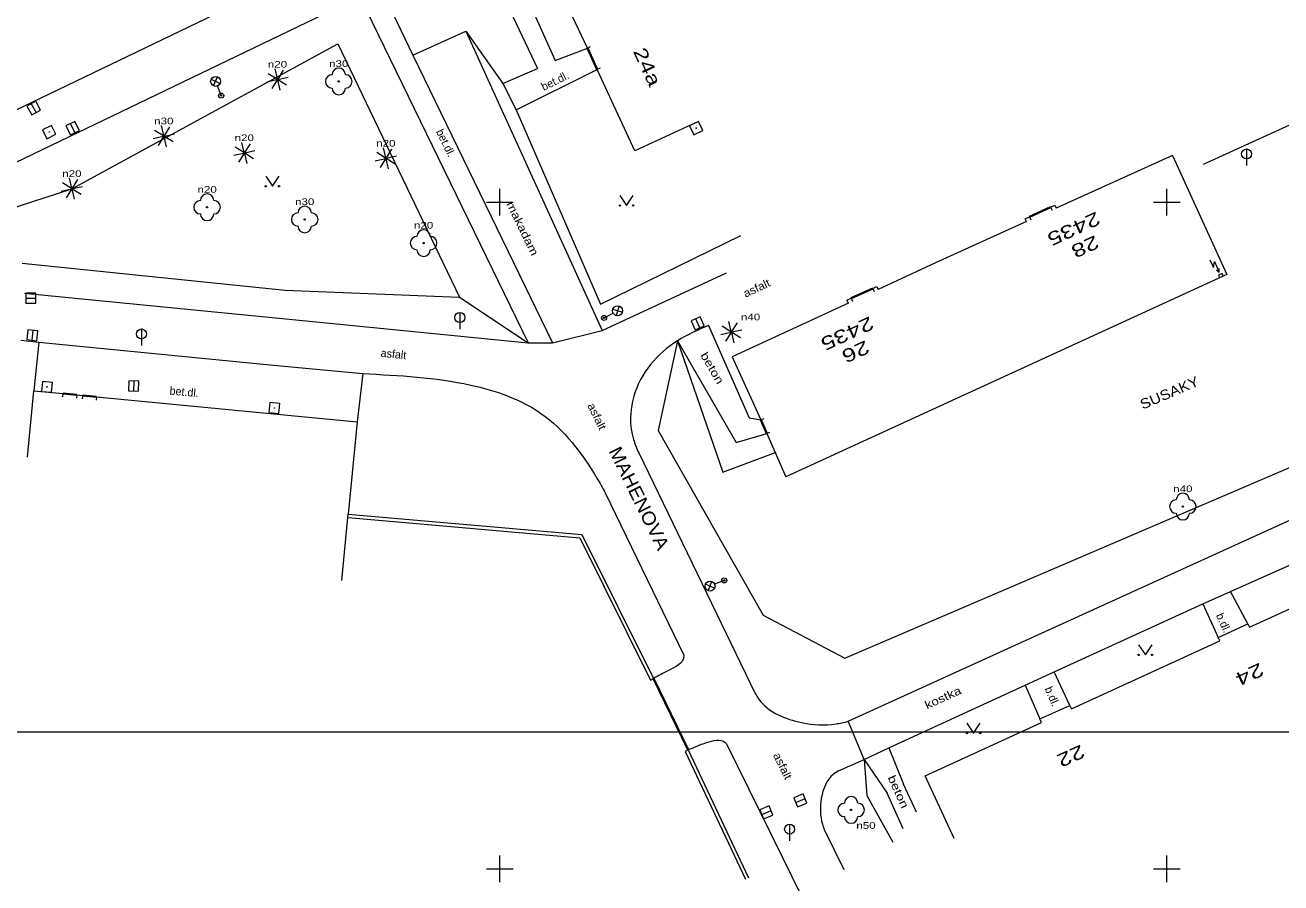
# Model space of a CAD drawing. Extents: x -670514 to -669423, y -1130798 to -1130123.
# Drawn here: x -670285.6 to -670191.5, y -1130401 to -1130336.7 of the extents above; entities that cross this region are included whole.
import ezdxf
from ezdxf.enums import TextEntityAlignment as Align

# ---------------------------------------------------------------- set-up
doc = ezdxf.new("R2010")
doc.units = 0
doc.header["$LTSCALE"] = 0.24
for name, color, linetype, lineweight in [('10', 7, 'Continuous', 13), ('11', 7, 'Continuous', 13), ('14', 7, 'Continuous', 13), ('22', 7, 'Continuous', 13), ('24', 7, 'Continuous', 13), ('26', 7, 'Continuous', 13), ('27', 7, 'Continuous', 13), ('33', 7, 'Continuous', 13), ('36', 7, 'Continuous', 13), ('45', 7, 'Continuous', 13), ('5', 7, 'Continuous', 13), ('6', 7, 'Continuous', 13), ('60', 7, 'Continuous', 13), ('61', 7, 'Continuous', 13), ('7', 7, 'Continuous', 13), ('8', 7, 'Continuous', 13)]:
    doc.layers.add(name, color=color, linetype=linetype, lineweight=lineweight)
for name, color, linetype in [('40', 7, 'Continuous'), ('42', 7, 'Continuous'), ('43', 7, 'Continuous'), ('44', 7, 'Continuous')]:
    doc.layers.add(name, color=color, linetype=linetype)

msp = doc.modelspace()

# ---------------------------------------------------------------- linework, layer by layer
at = {"layer": '10'}
for p, q in [((-670306.368, -1130352.764), (-670262.03, -1130331.413)), ((-670249.16, -1130332.047), (-670245.842, -1130339.387)), ((-670250.594, -1130332.729), (-670247.171, -1130339.983)), ((-670258.985, -1130333.841), (-670256.523, -1130338.99)), ((-670260.5, -1130334.581), (-670247.888, -1130360.543)), ((-670245.842, -1130339.387), (-670243.439, -1130338.448)), ((-670197.261, -1130347.166), (-670179.752, -1130339.172)), ((-670249.779, -1130341.113), (-670247.171, -1130339.983)), ((-670242.338, -1130359.631), (-670233.008, -1130355.298)), ((-670285.636, -1130356.823), (-670266.032, -1130358.753)), ((-670266.032, -1130358.753), (-670247.888, -1130360.543)), ((-670284.549, -1130360.498), (-670284.93, -1130364.149)), ((-670236.685, -1130360.389), (-670232.286, -1130368.017)), ((-670266.966, -1130362.23), (-670260.264, -1130362.861)), ((-670260.264, -1130362.861), (-670260.702, -1130366.465)), ((-670232.286, -1130368.017), (-670229.982, -1130367.337)), ((-670239.589, -1130368.794), (-670230.857, -1130386.843)), ((-670242.093, -1130371.791), (-670236.207, -1130383.981)), ((-670223.892, -1130388.929), (-670187.75, -1130372.448)), ((-670193.933, -1130381.622), (-670195.226, -1130379.206)), ((-670208.448, -1130385.217), (-670197.293, -1130380.124)), ((-670197.293, -1130380.124), (-670196.152, -1130382.65)), ((-670207.274, -1130387.732), (-670208.448, -1130385.217)), ((-670220.831, -1130390.914), (-670210.614, -1130386.221)), ((-670210.614, -1130386.221), (-670209.521, -1130388.748)), ((-670233.018, -1130390.607), (-670228.834, -1130399.092)), ((-670220.831, -1130390.914), (-670219.732, -1130393.646)), ((-670224.601, -1130392.647), (-670222.695, -1130391.791)), ((-670222.695, -1130391.791), (-670220.972, -1130394.327)), ((-670218.77, -1130395.747), (-670219.732, -1130393.646)), ((-670219.754, -1130396.986), (-670220.972, -1130394.327)), ((-670225.672, -1130397.1), (-670224.218, -1130400.048)), ((-670228.834, -1130399.092), (-670227.38, -1130402.04))]:
    msp.add_line(p, q, dxfattribs=at)
for points in [[(-670305.915, -1130356.591), (-670300.884, -1130354.022), (-670260.5, -1130334.581)], [(-670256.523, -1130338.99), (-670252.546, -1130337.184), (-670242.338, -1130359.631)], [(-670249.779, -1130341.113), (-670248.785, -1130343.091), (-670242.698, -1130340.067)], [(-670234.362, -1130359.254), (-670231.307, -1130366.18), (-670230.423, -1130366.329)], [(-670285.913, -1130360.345), (-670284.549, -1130360.498), (-670266.966, -1130362.23)], [(-670195.226, -1130379.206), (-670185.29, -1130374.784), (-670181.64, -1130377.99), (-670167.487, -1130371.008), (-670166.91, -1130368.462), (-670166.367, -1130366.06), (-670159.644, -1130362.991)]]:
    msp.add_lwpolyline(points, dxfattribs=at)
for points in [[(-670234.362, -1130359.254), (-670236.685, -1130360.389), (-670239.961, -1130364.559), (-670239.983, -1130367.799), (-670239.589, -1130368.794)], [(-670260.264, -1130362.861), (-670252.185, -1130363.716), (-670246.915, -1130365.843), (-670242.727, -1130370.686), (-670242.093, -1130371.791)], [(-670236.207, -1130383.981), (-670236.213, -1130384.104), (-670237.354, -1130385.122), (-670238.483, -1130385.731)], [(-670230.857, -1130386.843), (-670230.59, -1130387.259), (-670227.359, -1130389.028), (-670224.814, -1130389.125), (-670223.892, -1130388.929)], [(-670235.891, -1130391.078), (-670234.501, -1130390.523), (-670233.128, -1130390.506), (-670233.018, -1130390.607)], [(-670224.601, -1130392.647), (-670225.001, -1130392.908), (-670225.901, -1130394.687), (-670225.821, -1130396.643), (-670225.672, -1130397.1)]]:
    msp.add_spline(points, degree=3, dxfattribs=at)
at = {"layer": '11'}
for p, q in [((-670256.523, -1130338.99), (-670246.053, -1130360.545)), ((-670197.293, -1130380.124), (-670195.226, -1130379.206)), ((-670210.614, -1130386.221), (-670208.448, -1130385.217)), ((-670222.695, -1130391.791), (-670223.892, -1130388.929)), ((-670222.695, -1130391.791), (-670220.831, -1130390.914))]:
    msp.add_line(p, q, dxfattribs=at)
msp.add_lwpolyline([(-670247.888, -1130360.543), (-670246.053, -1130360.545), (-670242.338, -1130359.631)], dxfattribs=at)
at = {"layer": '14'}
msp.add_line((-670252.546, -1130337.184), (-670249.779, -1130341.113), dxfattribs=at)
for points in [[(-670282.08, -1130348.996), (-670262.15, -1130338.138), (-670253.016, -1130357.115)], [(-670248.785, -1130343.091), (-670242.447, -1130357.659), (-670231.924, -1130352.502)], [(-670300.884, -1130354.022), (-670295.798, -1130353.463), (-670282.08, -1130348.996)], [(-670285.8, -1130354.579), (-670266.083, -1130356.606), (-670253.016, -1130357.115), (-670247.888, -1130360.543)], [(-670236.685, -1130360.389), (-670238.138, -1130367.12), (-670230.255, -1130380.975), (-670224.134, -1130384.194), (-670162.927, -1130357.944)], [(-670236.685, -1130360.389), (-670233.289, -1130370.258), (-670229.288, -1130368.759)], [(-670222.695, -1130391.791), (-670222.481, -1130394.495), (-670220.535, -1130397.981)]]:
    msp.add_lwpolyline(points, dxfattribs=at)
at = {"layer": '22'}
for p, q in [((-670266.677, -1130340.762), (-670266.849, -1130340.008)), ((-670266.235, -1130340.112), (-670266.649, -1130340.768)), ((-670267.463, -1130340.982), (-670266.709, -1130340.81)), ((-670266.703, -1130340.782), (-670267.359, -1130340.368)), ((-670266.689, -1130340.836), (-670267.103, -1130341.492)), ((-670266.661, -1130340.842), (-670266.489, -1130341.596)), ((-670265.979, -1130341.236), (-670266.635, -1130340.822)), ((-670266.629, -1130340.794), (-670265.875, -1130340.622)), ((-670275.222, -1130345.033), (-670275.878, -1130344.619)), ((-670275.196, -1130345.013), (-670275.368, -1130344.259)), ((-670274.754, -1130344.363), (-670275.168, -1130345.019)), ((-670275.148, -1130345.045), (-670274.394, -1130344.873)), ((-670275.982, -1130345.233), (-670275.228, -1130345.061)), ((-670275.208, -1130345.087), (-670275.622, -1130345.743)), ((-670275.18, -1130345.093), (-670275.008, -1130345.847)), ((-670274.498, -1130345.487), (-670275.154, -1130345.073)), ((-670269.161, -1130346.271), (-670269.333, -1130345.517)), ((-670268.719, -1130345.621), (-670269.133, -1130346.277)), ((-670269.947, -1130346.491), (-670269.193, -1130346.319)), ((-670269.187, -1130346.291), (-670269.843, -1130345.877)), ((-670269.173, -1130346.345), (-670269.587, -1130347.001)), ((-670269.145, -1130346.351), (-670268.973, -1130347.105)), ((-670268.463, -1130346.745), (-670269.119, -1130346.331)), ((-670269.113, -1130346.303), (-670268.359, -1130346.131)), ((-670259.336, -1130346.901), (-670258.582, -1130346.729)), ((-670258.576, -1130346.701), (-670259.232, -1130346.287)), ((-670258.562, -1130346.755), (-670258.976, -1130347.411)), ((-670258.55, -1130346.681), (-670258.722, -1130345.927)), ((-670258.534, -1130346.761), (-670258.362, -1130347.515)), ((-670258.108, -1130346.031), (-670258.522, -1130346.687)), ((-670257.852, -1130347.155), (-670258.508, -1130346.741)), ((-670258.502, -1130346.713), (-670257.748, -1130346.541)), ((-670282.114, -1130348.976), (-670282.77, -1130348.562)), ((-670282.088, -1130348.956), (-670282.26, -1130348.202)), ((-670281.646, -1130348.306), (-670282.06, -1130348.962)), ((-670282.874, -1130349.176), (-670282.12, -1130349.004)), ((-670282.1, -1130349.03), (-670282.514, -1130349.686)), ((-670282.072, -1130349.036), (-670281.9, -1130349.79)), ((-670281.39, -1130349.43), (-670282.046, -1130349.016)), ((-670282.04, -1130348.988), (-670281.286, -1130348.816)), ((-670232.655, -1130359.706), (-670232.827, -1130358.952)), ((-670233.441, -1130359.926), (-670232.687, -1130359.754)), ((-670232.681, -1130359.726), (-670233.337, -1130359.312)), ((-670232.667, -1130359.78), (-670233.081, -1130360.436)), ((-670232.639, -1130359.786), (-670232.467, -1130360.54)), ((-670232.213, -1130359.056), (-670232.627, -1130359.712)), ((-670231.957, -1130360.18), (-670232.613, -1130359.766)), ((-670232.607, -1130359.738), (-670231.853, -1130359.566))]:
    msp.add_line(p, q, dxfattribs=at)
for centre, radius in [((-670266.669, -1130340.802), 0.04), ((-670262.075, -1130340.95), 0.05), ((-670275.188, -1130345.053), 0.04), ((-670269.153, -1130346.311), 0.04), ((-670258.542, -1130346.721), 0.04), ((-670282.08, -1130348.996), 0.04), ((-670271.941, -1130350.384), 0.05), ((-670264.628, -1130351.303), 0.05), ((-670255.713, -1130353.07), 0.05), ((-670232.647, -1130359.746), 0.04), ((-670198.802, -1130372.831), 0.05), ((-670223.667, -1130395.576), 0.05)]:
    msp.add_circle(centre, radius, dxfattribs=at)
for centre, start, end in [((-670262.075, -1130340.45), 0, 180), ((-670262.575, -1130340.95), 90, 270), ((-670261.575, -1130340.95), 270, 90), ((-670262.075, -1130341.45), 180, 0), ((-670271.941, -1130349.884), 0, 180), ((-670272.441, -1130350.384), 90, 270), ((-670271.441, -1130350.384), 270, 90), ((-670264.628, -1130350.803), 0, 180), ((-670271.941, -1130350.884), 180, 0), ((-670265.128, -1130351.303), 90, 270), ((-670264.128, -1130351.303), 270, 90), ((-670264.628, -1130351.803), 180, 0), ((-670255.713, -1130352.57), 0, 180), ((-670256.213, -1130353.07), 90, 270), ((-670255.213, -1130353.07), 270, 90), ((-670255.713, -1130353.57), 180, 0), ((-670198.802, -1130372.331), 0, 180), ((-670199.302, -1130372.831), 90, 270), ((-670198.302, -1130372.831), 270, 90), ((-670198.802, -1130373.331), 180, 0), ((-670223.667, -1130395.076), 0, 180), ((-670224.167, -1130395.576), 90, 270), ((-670223.167, -1130395.576), 270, 90), ((-670223.667, -1130396.076), 180, 0)]:
    msp.add_arc(centre, 0.5, start, end, dxfattribs=at)
at = {"layer": '24'}
for points in [[(-670196.772, -1130354.324), (-670196.511, -1130354.893), (-670196.44, -1130354.448), (-670196.075, -1130355.243)], [(-670196.277, -1130355.066), (-670196.075, -1130355.243), (-670196.077, -1130354.974)], [(-670195.772, -1130355.544), (-670195.856, -1130355.362), (-670196.128, -1130355.487), (-670196.045, -1130355.669)]]:
    msp.add_lwpolyline(points, dxfattribs=at)
at = {"layer": '26'}
for points in [[(-670235.451, -1130344.951), (-670234.778, -1130344.62), (-670235.109, -1130343.947), (-670235.782, -1130344.278)], [(-670284.28, -1130344.573), (-670283.949, -1130345.246), (-670283.276, -1130344.915), (-670283.607, -1130344.242)], [(-670284.364, -1130364.188), (-670283.617, -1130364.261), (-670283.544, -1130363.514), (-670284.291, -1130363.441)], [(-670267.31, -1130365.773), (-670266.564, -1130365.837), (-670266.5, -1130365.091), (-670267.246, -1130365.027)]]:
    msp.add_lwpolyline(points, close=True, dxfattribs=at)
for centre in [(-670283.778, -1130344.744), (-670235.28, -1130344.449), (-670283.9539, -1130363.851), (-670266.9049, -1130365.432)]:
    msp.add_circle(centre, 0.02, dxfattribs=at)
at = {"layer": '27'}
for p, q in [((-670285.119, -1130342.621), (-670284.761, -1130343.281)), ((-670282.184, -1130344.122), (-670281.854, -1130344.796)), ((-670194.022, -1130346.016), (-670194.022, -1130347.266)), ((-670285.533, -1130357.195), (-670284.783, -1130357.195)), ((-670252.997, -1130358.278), (-670252.997, -1130359.528)), ((-670235.012, -1130359.427), (-670235.32, -1130358.743)), ((-670285.007, -1130359.606), (-670285.085, -1130360.352)), ((-670276.867, -1130359.512), (-670276.867, -1130360.762)), ((-670277.428, -1130363.413), (-670277.47, -1130364.161)), ((-670227.819, -1130395.007), (-670227.123, -1130394.729)), ((-670230.365, -1130395.907), (-670229.669, -1130395.629)), ((-670228.277, -1130396.635), (-670228.277, -1130397.885))]:
    msp.add_line(p, q, dxfattribs=at)
for points in [[(-670285.448, -1130342.8), (-670285.09, -1130343.459), (-670284.431, -1130343.101), (-670284.788, -1130342.442)], [(-670282.52, -1130344.287), (-670282.19, -1130344.96), (-670281.516, -1130344.63), (-670281.846, -1130343.957)], [(-670285.533, -1130357.569), (-670284.783, -1130357.569), (-670284.783, -1130356.819), (-670285.533, -1130356.819)], [(-670234.671, -1130359.274), (-670234.979, -1130358.59), (-670235.663, -1130358.897), (-670235.355, -1130359.581)], [(-670285.378, -1130359.567), (-670285.457, -1130360.313), (-670284.712, -1130360.392), (-670284.633, -1130359.646)], [(-670277.802, -1130363.392), (-670277.843, -1130364.14), (-670277.094, -1130364.182), (-670277.053, -1130363.433)], [(-670227.681, -1130395.354), (-670226.984, -1130395.077), (-670227.262, -1130394.38), (-670227.958, -1130394.657)], [(-670230.227, -1130396.254), (-670229.53, -1130395.977), (-670229.808, -1130395.28), (-670230.504, -1130395.557)]]:
    msp.add_lwpolyline(points, close=True, dxfattribs=at)
for centre in [(-670194.0216, -1130346.3911), (-670252.9966, -1130358.6531), (-670276.8666, -1130359.8871), (-670228.2766, -1130397.0101)]:
    msp.add_circle(centre, 0.375, dxfattribs=at)
at = {"layer": '33'}
for p, q in [((-670271.645, -1130340.791), (-670270.959, -1130341.094)), ((-670271.454, -1130341.285), (-670271.151, -1130340.6)), ((-670270.887, -1130342.015), (-670271.167, -1130341.292)), ((-670241.532, -1130358.035), (-670240.815, -1130358.256)), ((-670241.063, -1130357.787), (-670241.285, -1130358.504)), ((-670242.191, -1130358.682), (-670241.506, -1130358.321)), ((-670233.9, -1130378.939), (-670234.59, -1130378.646)), ((-670234.391, -1130379.137), (-670234.099, -1130378.447)), ((-670233.179, -1130378.361), (-670233.897, -1130378.652))]:
    msp.add_line(p, q, dxfattribs=at)
for centre, radius in [((-670271.3022, -1130340.9426), 0.375), ((-670270.887, -1130342.015), 0.19), ((-670270.887, -1130342.015), 0.05), ((-670241.1738, -1130358.1456), 0.375), ((-670242.191, -1130358.682), 0.19), ((-670242.191, -1130358.682), 0.05), ((-670234.2451, -1130378.7922), 0.375), ((-670233.179, -1130378.361), 0.19), ((-670233.179, -1130378.361), 0.05)]:
    msp.add_circle(centre, radius, dxfattribs=at)
at = {"layer": '36'}
for points in [[(-670267.552, -1130348.056), (-670267.052, -1130348.806), (-670266.552, -1130348.056)], [(-670241.006, -1130349.5), (-670240.506, -1130350.25), (-670240.006, -1130349.5)], [(-670202.113, -1130383.203), (-670201.613, -1130383.953), (-670201.113, -1130383.203)], [(-670214.989, -1130389.059), (-670214.489, -1130389.809), (-670213.989, -1130389.059)]]:
    msp.add_lwpolyline(points, dxfattribs=at)
for centre in [(-670267.552, -1130348.806), (-670266.552, -1130348.806), (-670241.006, -1130350.25), (-670240.006, -1130350.25), (-670202.113, -1130383.953), (-670201.113, -1130383.953), (-670214.989, -1130389.809), (-670213.989, -1130389.809)]:
    msp.add_circle(centre, 0.05, dxfattribs=at)
at = {"layer": '5'}
for p, q in [((-670243.439, -1130338.448), (-670245.25, -1130334.578)), ((-670239.874, -1130346.165), (-670242.698, -1130340.067)), ((-670235.337, -1130344.064), (-670239.874, -1130346.165)), ((-670199.582, -1130346.504), (-670208.287, -1130350.454)), ((-670208.71, -1130350.368), (-670208.393, -1130350.221)), ((-670208.393, -1130350.221), (-670208.287, -1130350.454)), ((-670210.513, -1130351.465), (-670217.335, -1130354.56)), ((-670210.612, -1130351.249), (-670210.294, -1130351.101)), ((-670210.513, -1130351.465), (-670210.612, -1130351.249)), ((-670217.335, -1130354.56), (-670221.634, -1130356.547)), ((-670222.052, -1130356.475), (-670221.734, -1130356.331)), ((-670221.734, -1130356.331), (-670221.634, -1130356.547)), ((-670223.873, -1130357.583), (-670232.577, -1130361.607)), ((-670223.981, -1130357.347), (-670223.662, -1130357.202)), ((-670223.873, -1130357.583), (-670223.981, -1130357.347)), ((-670232.577, -1130361.607), (-670230.423, -1130366.329)), ((-670285.406, -1130369.126), (-670284.93, -1130364.149)), ((-670284.93, -1130364.149), (-670282.727, -1130364.361)), ((-670281.716, -1130364.448), (-670281.247, -1130364.504)), ((-670280.228, -1130364.605), (-670260.702, -1130366.465)), ((-670260.702, -1130366.465), (-670261.359, -1130373.392)), ((-670229.982, -1130367.337), (-670228.554, -1130370.61)), ((-670261.831, -1130378.37), (-670261.359, -1130373.392)), ((-670193.815, -1130381.88), (-670185.09, -1130377.885)), ((-670215.936, -1130397.717), (-670218.117, -1130393.008))]:
    msp.add_line(p, q, dxfattribs=at)
for points in [[(-670199.582, -1130346.504), (-670195.5, -1130355.419), (-670228.554, -1130370.61)], [(-670196.038, -1130382.898), (-670196.152, -1130382.65), (-670193.933, -1130381.622), (-670193.815, -1130381.88)], [(-670218.117, -1130393.008), (-670209.398, -1130389.016), (-670209.521, -1130388.748), (-670207.274, -1130387.732), (-670207.156, -1130387.989), (-670196.038, -1130382.898)]]:
    msp.add_lwpolyline(points, dxfattribs=at)
at = {"layer": '6'}
for p, q in [((-670243.439, -1130338.448), (-670243.211, -1130338.343)), ((-670242.47, -1130339.962), (-670242.698, -1130340.067)), ((-670208.71, -1130350.368), (-670208.605, -1130350.594)), ((-670210.294, -1130351.101), (-670210.189, -1130351.328)), ((-670222.052, -1130356.475), (-670221.949, -1130356.702)), ((-670223.662, -1130357.202), (-670223.559, -1130357.43)), ((-670282.748, -1130364.61), (-670282.727, -1130364.361)), ((-670281.716, -1130364.448), (-670281.737, -1130364.697)), ((-670281.271, -1130364.752), (-670281.247, -1130364.504)), ((-670280.228, -1130364.605), (-670280.252, -1130364.853)), ((-670230.423, -1130366.329), (-670230.193, -1130366.228)), ((-670229.982, -1130367.337), (-670229.753, -1130367.237))]:
    msp.add_line(p, q, dxfattribs=at)
at = {"layer": '6', "lineweight": 35}
for p, q in [((-670243.439, -1130338.448), (-670242.698, -1130340.067)), ((-670208.71, -1130350.368), (-670210.294, -1130351.101)), ((-670222.052, -1130356.475), (-670223.662, -1130357.202)), ((-670281.716, -1130364.448), (-670282.727, -1130364.361)), ((-670280.228, -1130364.605), (-670281.247, -1130364.504)), ((-670230.423, -1130366.329), (-670229.982, -1130367.337))]:
    msp.add_line(p, q, dxfattribs=at)
at = {"layer": '60'}
msp.add_lwpolyline([(-670513.627, -1130676.756), (-670103.627, -1130676.756), (-670103.627, -1130389.756), (-670513.627, -1130389.756)], close=True, dxfattribs=at)
at = {"layer": '61'}
for p, q in [((-670250, -1130351), (-670250, -1130349)), ((-670200, -1130351), (-670200, -1130349)), ((-670251, -1130350), (-670249, -1130350)), ((-670201, -1130350), (-670199, -1130350)), ((-670250, -1130401), (-670250, -1130399)), ((-670200, -1130401), (-670200, -1130399)), ((-670251, -1130400), (-670249, -1130400)), ((-670201, -1130400), (-670199, -1130400))]:
    msp.add_line(p, q, dxfattribs=at)
at = {"layer": '7'}
for p, q in [((-670236.117, -1130391.184), (-670231.589, -1130400.767)), ((-670235.891, -1130391.078), (-670231.363, -1130400.661))]:
    msp.add_line(p, q, dxfattribs=at)
for points in [[(-670261.38, -1130373.641), (-670244.009, -1130375.165), (-670238.706, -1130385.842)], [(-670261.359, -1130373.392), (-670243.848, -1130374.928), (-670238.483, -1130385.731)]]:
    msp.add_lwpolyline(points, dxfattribs=at)
at = {"layer": '8'}
for p, q in [((-670238.707, -1130385.84), (-670238.483, -1130385.731)), ((-670235.891, -1130391.078), (-670236.115, -1130391.187))]:
    msp.add_line(p, q, dxfattribs=at)
at = {"layer": '8', "lineweight": 35}
msp.add_line((-670235.891, -1130391.078), (-670238.483, -1130385.731), dxfattribs=at)

# ---------------------------------------------------------------- texts
at = {"layer": '22', "width": 1.3}
for s, p in [('n20', (-670266.6695, -1130339.916)), ('n30', (-670262.0745, -1130339.864)), ('n30', (-670275.1885, -1130344.167)), ('n20', (-670269.1535, -1130345.425)), ('n20', (-670258.5425, -1130345.835)), ('n20', (-670282.0805, -1130348.11)), ('n20', (-670271.9405, -1130349.298)), ('n30', (-670264.6275, -1130350.217)), ('n20', (-670255.7125, -1130351.984)), ('n40', (-670231.2035, -1130358.86)), ('n40', (-670198.8015, -1130371.745)), ('n50', (-670222.5515, -1130396.991))]:
    msp.add_text(s, height=0.499, dxfattribs=at).set_placement(p, align=Align.CENTER)
at = {"layer": '40'}
for s, rotation, p in [('bet.dl.', 26.418, (-670245.7295, -1130341.1819)), ('bet.dl.', 295.91, (-670254.3247, -1130345.6904)), ('asfalt', 354.318, (-670258.0007, -1130361.6862)), ('bet.dl.', 354.559, (-670273.6859, -1130364.5246)), ('b.dl.', 294.309, (-670196.0242, -1130381.6715)), ('b.dl.', 293.39, (-670208.8746, -1130387.1844))]:
    msp.add_text(s, height=0.6, rotation=rotation, dxfattribs=at).set_placement(p, align=Align.CENTER)
for s, rotation, width, p in [('makadam', 295.907, 1.25, (-670248.5696, -1130352.1039)), ('asfalt', 25.253, 1.1, (-670230.623, -1130356.717)), ('beton', 299.972, 1.3, (-670234.3411, -1130362.5936)), ('asfalt', 295.774, 1.1, (-670242.9913, -1130366.1941)), ('kostka', 24.54, 1.25, (-670216.6606, -1130387.4317)), ('asfalt', 296.248, 1.1, (-670229.0727, -1130392.4063)), ('beton', 294.611, 1.3, (-670220.403, -1130394.3341))]:
    msp.add_text(s, height=0.6, rotation=rotation, dxfattribs=dict(at, width=width)).set_placement(p, align=Align.CENTER)
at = {"layer": '42', "width": 1.15}
msp.add_text('SUSAKY', height=0.75, rotation=23.213, dxfattribs=at).set_placement((-670199.6588, -1130364.6419), align=Align.CENTER)
at = {"layer": '43', "width": 1.4}
for p in [(-670207.1784, -1130351.5511), (-670224.1574, -1130359.4021)]:
    msp.add_text('2435', height=1, rotation=204.595, dxfattribs=at).set_placement(p, align=Align.CENTER)
at = {"layer": '44'}
for s, rotation, width, p in [('24a', 294.849, 1.35, (-670239.3928, -1130340.0649)), ('28', 204.595, 1.4, (-670206.3279, -1130352.8914)), ('26', 204.595, 1.4, (-670223.5334, -1130360.7665)), ('24', 204.857, 1.45, (-670194.0058, -1130384.9619)), ('22', 204.331, 1.4, (-670207.39, -1130391.0776))]:
    msp.add_text(s, height=1, rotation=rotation, dxfattribs=dict(at, width=width)).set_placement(p, align=Align.CENTER)
at = {"layer": '45', "width": 1.1}
msp.add_text('MAHENOVA', height=1, rotation=296.253, dxfattribs=at).set_placement((-670240.0064, -1130372.4283), align=Align.CENTER)

doc.saveas('drawing.dxf')
